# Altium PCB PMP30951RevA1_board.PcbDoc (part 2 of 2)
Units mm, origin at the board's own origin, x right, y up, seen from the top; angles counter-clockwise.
Board outline 87.63 x 58.42 mm, 2 copper layers (Top Layer, Bottom Layer), stack 1.575 mm thick; 82 components, 35 nets, 177 pads, 49 vias.
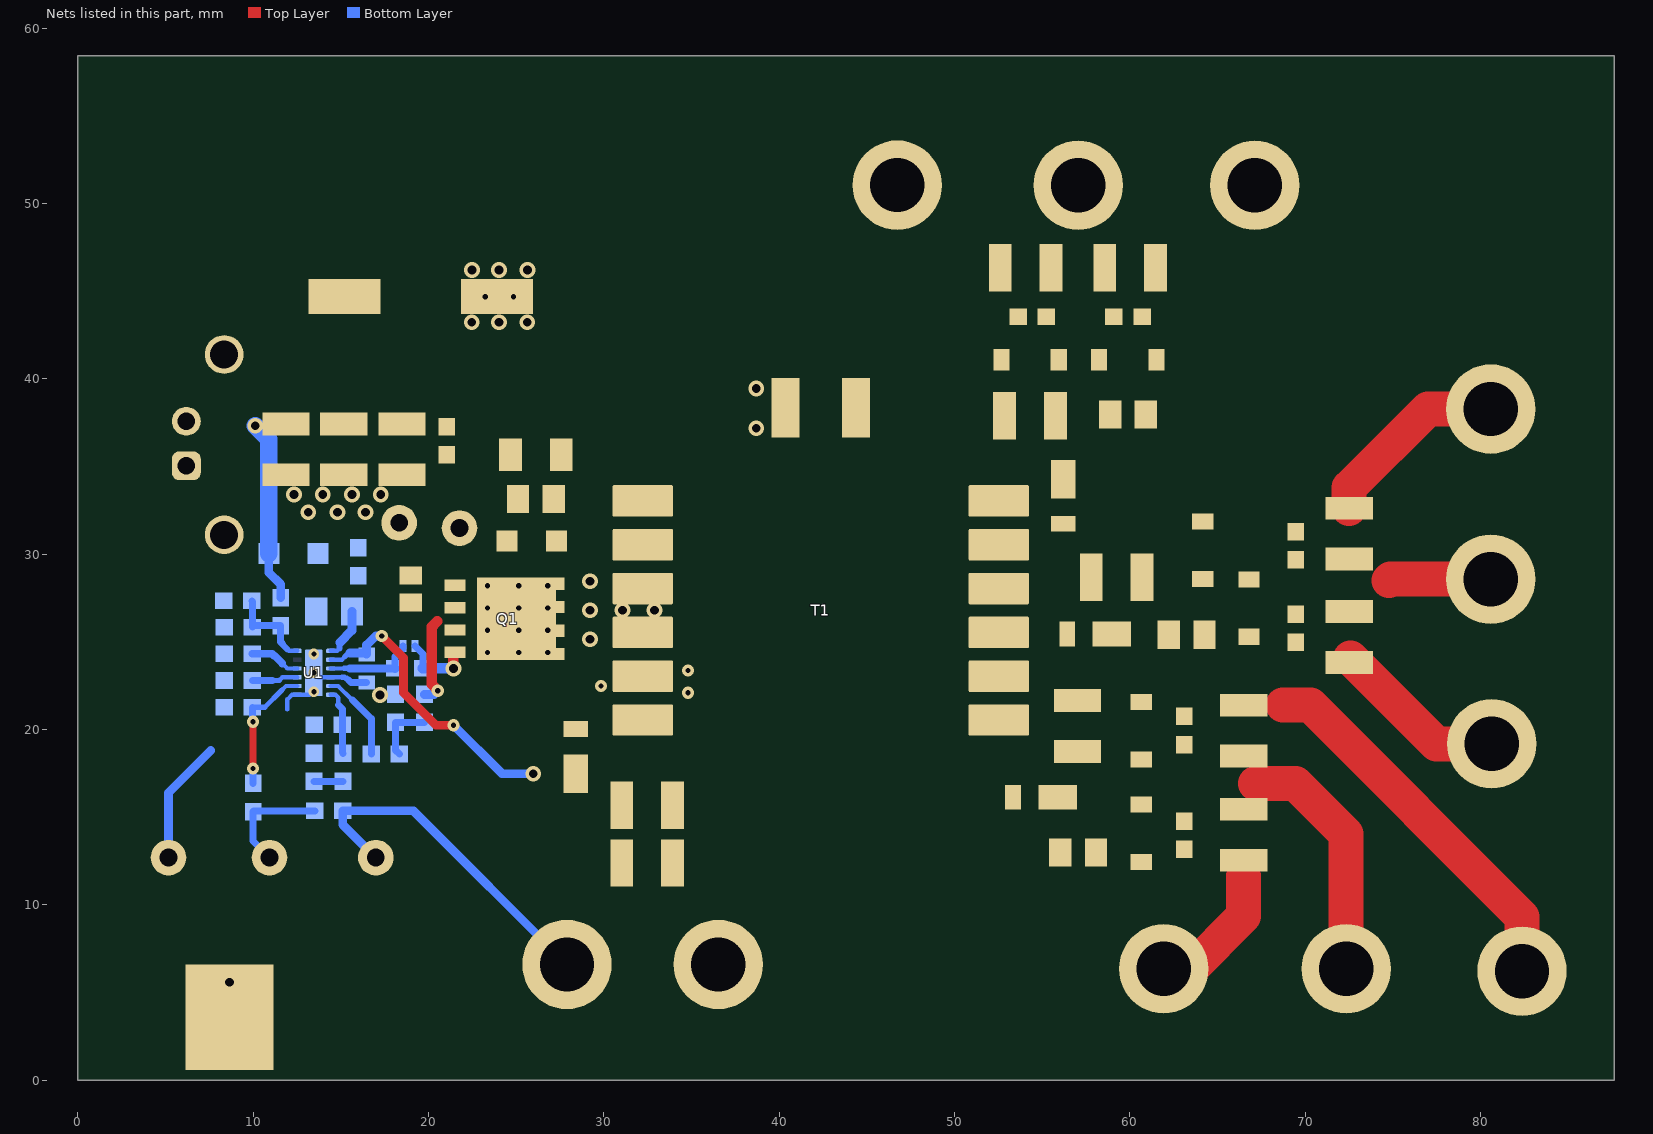
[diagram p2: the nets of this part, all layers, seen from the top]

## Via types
v1: diameter 0.9, hole 0.5, Top Layer to Bottom Layer, tented top, 19 vias
v2: diameter 0.7, hole 0.3, Top Layer to Bottom Layer, 16 vias
v3: diameter 0.9, hole 0.5, Top Layer to Bottom Layer, 4 vias
v4: diameter 0.7, hole 0.3, Top Layer to Bottom Layer, tented top, 3 vias
v5: diameter 0.7, hole 0.3, Top Layer to Bottom Layer, tented bottom, 3 vias
v6: diameter 0.6, hole 0.3, Top Layer to Bottom Layer, 3 vias
v7: diameter 0.9, hole 0.5, Top Layer to Bottom Layer, tented bottom, 1 vias

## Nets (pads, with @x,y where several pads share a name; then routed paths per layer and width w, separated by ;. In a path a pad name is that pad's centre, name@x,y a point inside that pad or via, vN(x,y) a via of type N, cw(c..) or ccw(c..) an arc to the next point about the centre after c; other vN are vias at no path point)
10Vaux: +10V_pri.1 C16.1 C24.1 C25.1 D12.1 R18.2 TP6.1 U1.2 | length 36.8
  Top Layer w0.5: v2(17.33,25.328) 18.575,24.084 18.575,22.091 20.423,20.243 v2(21.421,20.243)
  Bottom Layer w0.25: U1.2@14.412,23.978 15.062,23.978 15.211,24.126
  Bottom Layer w0.3: 15.211,24.126 15.437,24.353 15.508,24.353
  Bottom Layer w0.5: 15.508,24.353 16.398,24.353 C16.1@16.468,24.283 16.468,24.814 16.983,25.328 v2(17.33,25.328) ; TP6.1@16.992,12.688 15.109,14.571 R18.2@15.109,15.355 19.135,15.355 +10V_pri.1@27.898,6.592 ; v2(21.421,20.243) 24.196,17.468 v3(25.974,17.468)
GND: C1.2 C2.2 C3.2 C4.2 C5.2 C13.2 C16.2 C17.2 C19.2 C20.2 C21.2 C22.2 C23.2 C24.2 C25.2 GND_pri.1 Jmp1.1 pad.17 R16.1 R19.1 R20.1 R22.1 T1.5 TP2.1 TP7.1 TP8.1 U1.4 U1.7 U1.13@13.462,23.228 | length 12
  Bottom Layer w0.25: 11.948,21.136 11.948,21.712 12.214,21.978 U1.7@12.512,21.978 U1.13@13.212,21.978 ; U1.13@13.712,22.978 U1.4@14.412,22.978 15.062,22.978
  Bottom Layer w0.3: 15.062,22.978 15.209,22.978 15.265,22.922 15.331,22.922 15.437,22.816 15.437,22.81 15.468,22.778
  Bottom Layer w0.4: 15.437,22.816 15.57,22.683 C16.2@16.468,22.683
  Bottom Layer w0.5: TP8.1@5.165,12.688 5.165,16.389 7.575,18.799
  other v1: 13.132,32.385 14.808,32.385 16.408,32.385 12.319,33.401 13.97,33.401 15.628,33.401 17.272,33.401 22.47,43.234 24.018,43.234 25.637,43.234 22.479,46.205 24.027,46.205 25.646,46.205
  other v2: 23.241,44.679 24.841,44.679
  other v3: 38.693,37.176 38.693,39.442
  other v4: 34.798,22.098 29.845,22.479 34.798,23.368
  other v6: 13.462,22.153 13.462,23.228 13.462,24.303
  other v7: 17.23,21.959
Net+15V_1_1: +15V_1.1 C7.1 D2.1 R1.2 R3.2 | length 8.1
  Top Layer w2: +15V_1.1@61.934,6.338 63.488,6.338 66.502,9.352 66.502,11.642
Net+15V_2_1: +15V_2.1 C10.1 D7.1 R5.2 R7.2 | length 10.1
  Top Layer w2: C10.1@72.602,24.085 77.51,19.177 +15V_2.1@80.645,19.177
Net+15V_3_1: +15V_3.1 C14.1 D11.1 R11.2 R12.2
Net-5V_1_1: -5V_1.1 C8.2 C9.2 D3.2 R4.1 T1.8 | length 21.7
  Top Layer w2: 68.744,21.385 70.303,21.385 82.381,9.307 -5V_1.1@82.381,6.211
Net-5V_2_1: -5V_2.1 C11.2 C12.2 D8.2 R9.1 T1.10 | length 11.1
  Top Layer w2: C12.2@72.517,32.618 72.517,33.788 77.005,38.276 -5V_2.1@80.603,38.276
Net-5V_3_1: -5V_3.1 C15.2 C18.2 C19.1 D13.2 R15.1 T1.12
NetC6_2: C6.2 D4.1 R2.1
NetC7_2: C7.2 C9.1 D2.2 D3.1 R3.1 R4.2 rtn_1.1 | length 14.1
  Top Layer w2: 67.183,16.924 69.446,16.924 72.348,14.023 rtn_1.1@72.348,6.338
NetC8_1: C8.1 D1.1 R1.1
NetC10_2: C10.2 C12.1 D7.2 D8.1 R7.1 R9.2 rtn_2.1 | length 5.9
  Top Layer w2: 74.783,28.484 74.872,28.572 rtn_2.1@80.603,28.572
NetC11_1: C11.1 D5.1 R5.1
NetC13_1: C13.1 R8.1 U1.1 | length 3
  Bottom Layer w0.25: U1.1@14.412,24.478 14.784,24.478 14.931,24.625
  Bottom Layer w0.35: 14.931,24.625 14.931,24.953
  Bottom Layer w0.5: 14.931,24.953 15.628,25.65 C13.1@15.628,26.725
NetC14_2: C14.2 C18.1 D11.2 D13.1 R12.1 R15.2 rtn_3.1
NetC15_1: C15.1 D9.1 R11.1
NetC17_1: C17.1 R13.2 R14.1 | length 3.5
  Bottom Layer w0.4: R13.2@18.333,18.597 18.119,18.811 C17.1@18.119,20.397 R14.1@19.77,20.397
NetC20_1: C20.1 R6.1 R19.2 U1.12 | length 5.3
  Bottom Layer w0.25: 11.948,24.567 12.037,24.478 U1.12@12.512,24.478
  Bottom Layer w0.35: 11.664,24.886 11.664,24.851 11.948,24.567
  Bottom Layer w0.4: R19.2@9.925,27.334 9.951,27.308 C20.1@9.951,25.836 10.04,25.925 R6.1@11.564,25.925 11.564,24.986 11.664,24.886
NetC21_1: C21.1 R21.2 U1.6 | length 3.8
  Bottom Layer w0.25: U1.6@14.412,21.978 14.694,21.978 14.859,21.813 14.859,21.395
  Bottom Layer w0.4: 14.859,21.395 15.081,21.172 C21.1@15.081,20.269 15.081,18.674 R21.2@15.12,18.635
NetC22_1: C22.1 U1.9 | length 2.6
  Bottom Layer w0.25: 11.496,22.81 11.664,22.978 U1.9@12.512,22.978
  Bottom Layer w0.3: 11.089,22.788 11.474,22.788 11.496,22.81
  Bottom Layer w0.4: C22.1@9.951,22.788 11.089,22.788
NetC23_1: C23.1 R21.1 | length 1.7
  Bottom Layer w0.4: C23.1@13.469,17.035 R21.1@15.12,17.035
NetD1_2: D1.2 T1.7
NetD5_2: D5.2 T1.9
NetD6_1: D6.1 R8.2
NetD9_2: D9.2 T1.11
NetD10_1: D10.1 R10.1 U1.3 | length 5.1
  Bottom Layer w0.25: U1.3@14.412,23.478 15.179,23.478 15.184,23.483
  Bottom Layer w0.3: 15.184,23.483 15.495,23.483 15.508,23.469
  Bottom Layer w0.4: R10.1@18.081,23.483 18.081,24.153 18.531,24.603 D10.1@18.531,24.753
  Bottom Layer w0.45: 15.508,23.469 R10.1@18.067,23.469
  Bottom Layer w0.5: R10.1@18.067,23.469 R10.1@18.081,23.483
NetD10_2: D10.2 Q1.4 R10.2 | length 4.2
  Top Layer w0.6: v3(21.421,23.483) 21.421,24.31 Q1.4@21.515,24.404
  Bottom Layer w0.4: D10.2@19.231,24.753 19.681,24.303 R10.2@19.681,23.483
  Bottom Layer w0.6: R10.2@19.681,23.483 v3(21.421,23.483)
NetQ1_1: Q1.1 Q1.2 Q1.3 R14.2 R16.2 | length 5.1
  Top Layer w0.6: 20.504,26.175 20.174,25.845 20.174,22.571 v5(20.532,22.213)
  Bottom Layer w0.5: R14.2@19.77,21.997 20.316,21.997 v5(20.532,22.213)
NetR13_1: R13.1 U1.5 | length 5.1
  Bottom Layer w0.25: U1.5@14.412,22.478 14.84,22.478 15.628,21.691 15.671,21.691 15.671,21.678
  Bottom Layer w0.4: 15.671,21.678 16.72,20.629 16.733,20.629 R13.1@16.733,18.597
NetR17_1: R17.1 R22.2 U1.8 | length 7.4
  Top Layer w0.4: v5(9.991,17.768) v5(9.991,20.435)
  Bottom Layer w0.25: 11.603,22.213 11.868,22.478 U1.8@12.512,22.478
  Bottom Layer w0.3: R22.2@9.951,21.264 10.654,21.264 11.603,22.213
  Bottom Layer w0.4: R22.2@9.951,21.264 9.951,20.475 v5(9.991,20.435) ; R17.1@9.991,16.917 v5(9.991,17.768)
NetR17_2: R17.2 R18.1 TP5.1 | length 6.6
  Bottom Layer w0.4: TP5.1@10.929,12.688 9.991,13.626 R17.2@9.991,15.317 10.029,15.355 R18.1@13.509,15.355
NetR20_2: R20.2 U1.10 | length 2.9
  Bottom Layer w0.25: 11.664,23.762 11.948,23.478 U1.10@12.512,23.478
  Bottom Layer w0.435: R20.2@9.951,24.312 11.08,24.312 11.183,24.209 11.217,24.209 11.664,23.762
SW-aux: D12.2 T1.6
SW_primary: D4.2 Q1.5 Q1.6 Q1.7 Q1.8 Q1.9 T1.3 T1.4 TP3.1
  other v1: 29.21,25.146 29.21,26.797 31.07,26.797 32.893,26.797 29.21,28.448
  other v2: 23.368,24.384 25.146,24.384 26.797,24.384 23.368,25.654 25.146,25.654 26.797,25.654 23.368,26.924 25.146,26.924 26.797,26.924 23.368,28.194 25.146,28.194 26.797,28.194
VIN: C1.1 C2.1 C3.1 C4.1 C5.1 C6.1 D6.2 Jmp1.2 R2.2 R6.2 T1.1 T1.2 TP1.1 | length 10.4
  Bottom Layer w0.5: D6.2@10.889,30.036 10.889,28.95 11.564,28.275 R6.2@11.564,27.525
  Bottom Layer w1: v1(10.118,37.326) 10.889,36.555 D6.2@10.889,30.036
pads on no net: U1.11 U1.13@13.462,22.543 U1.13@13.462,23.913

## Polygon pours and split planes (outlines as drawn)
Net+15V_1_1 on Top Layer "TOP_LAYER_NET+15V_1_1_P034" (solid, remove dead copper, pour order 34): 57.398,11.96 58.817,10.541 67.867,10.541 68.744,11.418 68.744,13.095 68.138,13.701 59.819,13.701 59.189,14.33 57.736,14.33 57.398,13.992
Net-5V_1_1 on Top Layer "TOP_LAYER_NET-5V_1_1_P033" (solid, remove dead copper, pour order 33): 50.8,22.098 54.455,22.098 56.36,20.193 68.662,20.193 69.446,20.977 69.446,21.841 68.744,22.543 64.582,22.543 63.552,23.573 57.697,23.573 57.307,23.963 50.804,23.963
NetC7_2 on Top Layer "TOP_LAYER_NETC7_2_P032" (solid, remove dead copper, pour order 32): 59.991,15.256 61.023,14.224 68.157,14.224 68.453,14.52 68.453,19.329 68.102,19.68 60.874,19.68 59.991,18.796
NetC8_1 on Top Layer "TOP_LAYER_NETC8_1_P030" (solid, remove dead copper, pour order 30): 54.805,11.991 55.071,11.725 56.532,11.725 57.057,12.251 57.057,14.426 58.373,15.742 58.373,19.572 58.157,19.788 55.227,19.788 54.805,19.365
NetD1_2 on Top Layer "TOP_LAYER_NETD1_2_P029" (solid, remove dead copper, pour order 29): 50.488,16.51 ccw(c52.282,16.51) 52.282,14.717 53.285,14.717 ccw(c53.285,15.742) 54.31,15.742 54.31,21.299 ccw(c53.966,21.299) 53.966,21.643 51.154,21.643 ccw(c51.154,20.977) 50.488,20.977
Net+15V_2_1 on Top Layer "TOP_LAYER_NET+15V_2_1_P028" (solid, remove dead copper, pour order 28): 63.552,26.416 63.552,24.162 64.854,22.86 74.364,22.86 75.235,23.731 75.235,25.034 74.741,25.527 67.722,25.527 66.514,26.735 63.871,26.735
NetC10_2 on Top Layer "TOP_LAYER_NETC10_2_P027" (solid, remove dead copper, pour order 27): 63.552,27.403 66.499,27.403 67.867,26.035 74.285,26.035 75.235,26.985 75.235,29.457 74.339,30.353 64.554,30.353 63.552,29.351
NetC11_1 on Top Layer "TOP_LAYER_NETC11_1_P026" (solid, remove dead copper, pour order 26): 57.802,26.447 58.851,26.447 59.743,27.34 59.743,29.627 60.156,30.04 61.4,30.04 62.865,28.575 62.865,24.404 62.596,24.135 58.108,24.135 57.802,24.441
Net-5V_2_1 on Top Layer "TOP_LAYER_NET-5V_2_1_P025" (solid, remove dead copper, pour order 25): 50.804,28.941 55.553,28.941 60.267,33.655 74.803,33.655 75.235,33.223 75.235,30.986 74.982,30.734 60.19,30.734 59.496,30.04 59.496,27.801 58.883,27.189 50.777,27.189
NetD5_2 on Top Layer "TOP_LAYER_NETD5_2_P023" (solid, remove dead copper, pour order 23): 56.769,26.447 cw(c56.769,25.994) 57.222,25.994 57.222,24.941 cw(c56.902,24.941) 56.902,24.62 50.883,24.62 cw(c50.883,25.014) 50.488,25.014 50.488,25.908 cw(c51.028,25.908) 51.028,26.447
Net+15V_3_1 on Top Layer "TOP_LAYER_NET+15V_3_1_P022" (solid, remove dead copper, pour order 22): 60.156,49.459 63.009,52.312 67.966,52.312 67.966,50.818 66.502,49.354 66.502,41.092 62.101,36.691 60.156,36.691
NetC14_2 on Top Layer "TOP_LAYER_NETC14_2_P021" (solid, remove dead copper, pour order 21): 59.394,40.437 59.584,40.628 59.584,51.986 58.243,53.328 55.899,53.328 54.695,52.124 54.695,40.437
NetC15_1 on Top Layer "TOP_LAYER_NETC15_1_P020" (solid, remove dead copper, pour order 20): 55.01,33.035 58.243,33.035 59.496,34.288 59.496,38.973 59.027,39.442 55.01,39.442
NetD9_2 on Top Layer "TOP_LAYER_NETD9_2_P019" (solid, remove dead copper, pour order 19): 51.028,29.576 54.309,29.576 ccw(c54.309,32.116) 56.105,30.32 56.549,30.764 ccw(c55.323,31.99) 57.057,31.99 57.057,32.176 ccw(c56.807,32.176) 56.807,32.426 56.041,32.426 ccw(c56.041,31.053) 55.071,32.024 54.898,31.851 cw(c53.992,32.758) 53.992,31.476 50.877,31.476 ccw(c50.877,30.976) 50.377,30.976 50.377,29.938 ccw(c50.758,29.938) 50.758,29.557
Net-5V_3_1 on Top Layer "TOP_LAYER_NET-5V_3_1_P018" (solid, remove dead copper, pour order 18): 54.314,32.176 47.743,32.176 43.519,36.4 43.519,50.026 45.424,51.931 50.758,51.931 54.06,48.629 54.06,36.801 54.56,36.301 54.56,32.404 54.385,32.229
GND on Top Layer "TOP_LAYER_GND_P017" (solid, remove dead copper, pour order 17): 41.106,36.075 38.101,36.075 37.677,36.499 37.677,40.247 38.058,40.628 41.106,40.628
GND on Top Layer "TOP_LAYER_GND_P016" (solid, remove dead copper, pour order 16): 20.696,47.486 20.696,44.359 22.268,42.787 25.828,42.787 27.225,44.184 27.225,47.486
GND on Top Layer "TOP_LAYER_GND_P012" (solid, remove dead copper, pour order 12): 31.993,17.133 31.993,6.318 34.259,4.052 37.925,4.052 41.106,7.233 41.106,17.051
10Vaux on Top Layer "TOP_LAYER_10VAUX_P000" (solid, remove dead copper, pour order 0): 30.244,18.597 31.708,17.133 31.708,6.273 29.487,4.052 26.519,4.052 24.487,6.084 24.487,16.915 26.169,18.597
SW-aux on Top Layer "TOP_LAYER_SW-AUX_P001" (solid, remove dead copper, pour order 1): 34.121,21.324 34.121,20.01 cw(c33.359,20.01) 33.359,19.248 28.032,19.248 cw(c28.032,19.888) 27.392,19.888 27.392,20.437 cw(c28.533,20.437) 28.533,21.578 33.867,21.578 cw(c33.867,21.324)
GND on Top Layer "TOP_LAYER_GND_P006" (solid, remove dead copper, pour order 6): 24.235,9.121 24.235,6.141 22.146,4.052 5.546,4.052 4.403,5.195 4.403,15.359 4.403,36.175 22.235,36.175 23,35.41 23,33.474 22.743,33.218 20.832,33.218 20.083,32.469 20.083,30.612 20.659,30.036 20.659,29.104 19.83,28.275 18.22,28.275 17.754,27.809 17.754,26.404 17.983,26.175 19.363,26.175 22.463,23.075 28.97,23.075 29.759,23.864 39.021,23.864 41.106,21.779 41.106,10.656 39.571,9.121
NetQ1_1 on Top Layer "TOP_LAYER_NETQ1_1_P005" (solid, remove dead copper, pour order 5): 22.146,25.328 19.365,25.328 18.133,26.561 18.133,27.721 18.221,27.809 19.75,27.809 20.56,28.619 22.146,28.619
NetC6_2 on Top Layer "TOP_LAYER_NETC6_2_P004" (solid, remove dead copper, pour order 4): 26.445,30.036 28.064,30.036 28.528,30.5 28.528,36.371 28.198,36.701 26.746,36.701 26.445,36.4
SW_primary on Top Layer "TOP_LAYER_SW_PRIMARY_P003" (solid, remove dead copper, pour order 3): 40.407,29.007 cw(c40.407,28.309) 41.106,28.309 41.106,25.067 cw(c40.376,25.067) 40.376,24.337 33.126,24.341 29.214,24.341 ccw(c29.214,23.377) 28.532,24.059 28.531,24.058 cw(c27.568,25.021) 27.568,23.659 23.14,23.659 cw(c23.14,24.126) 22.672,24.126 22.672,28.525 ccw(c21.434,28.309) 22.323,29.197 20.974,30.546 cw(c22.206,31.778) 20.464,31.778 cw(c21.504,31.778) 21.504,32.817 22.285,32.817 cw(c22.285,32.238) 22.865,32.238 ccw(c23.325,32.238) 23.325,31.778 24.811,31.778 cw(c24.811,31.118) 25.47,31.118 25.47,29.782 ccw(c26.245,29.782) 26.245,29.007
VIN on Top Layer "TOP_LAYER_VIN_P002" (solid, remove dead copper, pour order 2): 4.403,36.818 22.323,36.818 23.54,35.601 23.54,32.819 24.24,32.119 25.829,32.119 26.12,32.41 26.12,36.376 26.77,37.026 28.848,37.026 29.398,36.476 29.398,30.005 30.12,29.284 33.938,29.284 34.375,29.72 34.375,39.866 31.747,42.494 19.726,42.494 18.037,44.184 18.037,46.201 17.133,47.105 6.181,47.105 4.403,45.327
SW_primary on Bottom Layer "BOTTOM_LAYER_SW_PRIMARY_P035" (solid, remove dead copper, pour order 35): 33.856,29.009 cw(c33.856,28.321) 34.544,28.321 34.544,26.009 cw(c32.004,26.009) 32.004,23.469 23.115,23.469 cw(c23.115,24.183) 22.401,24.183 22.401,28.068 ccw(c19.861,28.068) 21.657,29.864 20.974,30.546 cw(c22.206,31.778) 20.464,31.778 cw(c21.504,31.778) 21.504,32.817 21.895,32.817 cw(c21.895,30.913) 23.241,32.26 23.325,32.176 ccw(c24.468,33.319) 24.468,31.703 25.123,31.703 cw(c25.123,30.901) 25.924,30.901 25.924,29.611 ccw(c26.527,29.611) 26.527,29.009
GND on Bottom Layer "BOTTOM_LAYER_GND_P015" (solid, remove dead copper, pour order 15): 4.403,29.499 19.627,29.499 20.083,29.954 20.083,32.469 20.832,33.218 23.141,33.218 24.24,32.119 25.829,32.119 26.12,32.41 26.12,36.376 26.77,37.026 28.848,37.026 29.398,36.476 29.398,30.005 30.116,29.287 34.89,29.287 35.137,29.041 35.137,24.738 33.474,23.075 28.97,23.075 22.879,23.075 17.193,17.389 17.193,15.699 15.314,13.82 8.583,13.82 4.403,9.64 4.403,5.195 5.546,4.052 37.925,4.052 41.106,7.233 41.106,46.513 37.677,49.942 5.589,49.942 4.403,48.756
NetD6_1 on Bottom Layer "BOTTOM_LAYER_NETD6_1_P013" (solid, remove dead copper, pour order 13): 14.44,29.417 14.895,29.872 16.544,29.872 16.708,30.036 16.708,31.094 16.492,31.311 13.158,31.311 12.912,31.065 12.912,29.499 12.994,29.417
NetC13_1 on Bottom Layer "BOTTOM_LAYER_NETC13_1_P011" (solid, remove dead copper, pour order 11): 14.931,25.709 16.535,25.709 17.23,26.404 17.23,28.817 16.722,29.325 14.994,29.325 14.796,29.127 14.796,25.844
GND on Bottom Layer "BOTTOM_LAYER_GND_P010" (solid, remove dead copper, pour order 10): 10.322,20.435 9.349,20.435 9.151,20.632 9.151,27.734 8.721,28.165 7.088,28.165 6.689,27.765 6.689,18.343 7.197,17.835 11.036,17.835 12.277,19.076 12.277,21.814 12.079,22.011
GND on Bottom Layer "BOTTOM_LAYER_GND_P009" (solid, remove dead copper, pour order 9): 13.962,22.478 13.962,21.063 14.281,20.744 14.281,17.922 14.194,17.835 12.714,17.835 12.628,17.921 12.628,21.343 12.963,21.678 12.963,22.478
GND on Bottom Layer "BOTTOM_LAYER_GND_P008" (solid, remove dead copper, pour order 8): 13.874,30.361 11.214,30.361 10.889,30.036 10.889,28.506 12.289,27.106 12.289,25.401 12.963,24.728 12.963,23.712 13.962,23.711 13.962,24.922 14.423,25.4 14.423,29.813
GND on Bottom Layer "BOTTOM_LAYER_GND_P007" (solid, remove dead copper, pour order 7): 15.743,22.153 16.699,21.197 18.594,21.197 18.844,21.447 18.844,22.478 18.575,22.747 17.38,22.747 17.152,22.975 15.833,22.975 15.743,22.885

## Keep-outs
Keep-Out Layer:
  text ".Layer_Name" at 14.656,-21.806 h1.52

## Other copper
Top Layer:
  text ".Layer_Name" at 14.656,-21.806 h1.52
Bottom Layer:
  text ".Layer_Name" at 14.656,-21.806 h1.52

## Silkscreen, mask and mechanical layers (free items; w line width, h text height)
Top Overlay:
  text "12/2020" at 81.475,56.877 h0.8
  text "'.PRJ_Number'.PCB_Rev" at 6.604,53.213 h2
  text "PSR Flyback" at 10.329,51.356 h1
  text "VIN" at 3.832,37.076 h1 r90
  text "GND" at 3.832,32.437 h1 r90
  text "AGND" at 3.332,9.827 h1
  text "NWA" at 9.3,9.827 h1
  text "priFB" at 15.124,9.624 h1
  text ".Layer_Name" at 14.656,-21.806 h1.52
Bottom Overlay:
  text ".Layer_Name" at 14.656,-21.806 h1.52
Top Paste:
  text ".Layer_Name" at 14.656,-21.806 h1.52
Bottom Paste:
  text ".Layer_Name" at 14.656,-21.806 h1.52
Top Solder:
  text ".Layer_Name" at 14.656,-21.806 h1.52
  text ".Layer_Name" at 14.656,-21.806 h1.52
Bottom Solder:
  text "'.PRJ_Number'.PCB_Rev" at 37.211,13.82 h2 r270
  text ".Layer_Name" at 14.656,-21.806 h1.52
Drill Guide:
  text ".Layer_Name" at 14.656,-21.806 h1.52
M1 Board Outline:
  the board outline again, w0.254
  text ".Layer_Name" at 14.656,-21.806 h1.52
M2 Board Dimensions:
  rectangle: 0,-6.985 3.175,-3.81
  rectangle: 3.175,-10.16 12.7,-6.985
  lines w0.178: 0,-6.985 25.4,-6.985 ; 3.175,-10.16 3.175,-3.81 ; 6.35,-10.16 6.35,-3.81 ; 12.7,-10.16 12.7,-3.81 ; 19.05,-10.16 19.05,-3.81 ; 0,-10.16 25.4,-10.16 25.4,-3.81 0,-3.81 0,-10.16
  text ".Layer_Name" at 14.656,-21.806 h1.52
M3 3D STEP Top:
  text ".Layer_Name" at 14.656,-21.806 h1.52
M4 3D STEP Bottom:
  text ".Layer_Name" at 14.656,-21.806 h1.52
M5 Assembly Top:
  lines w0.254: -7.417,-23.626 160.223,-23.626 ; -7.417,-18.462 160.274,-18.462 ; -7.417,-13.297 -7.417,-28.791 94.31,-28.791 160.274,-28.791 160.274,-13.297 -7.404,-13.297 -7.404,-28.791 32.614,-28.791 ; 55.194,-28.791 55.194,-13.297 ; 87.376,-18.462 87.376,-13.297 ; 108.712,-18.462 108.712,-13.297 ; 124.511,-28.956 124.511,-23.804
  text "COMPONENTS MARKED 'DNP' SHOULD NOT BE POPULATED." at 29.299,-8.09 h1.52
  text "ASSEMBLY VARIANT:" at 29.286,-11.024 h1.52
  text ".VariantName" at 55.601,-11.024 h1.52
  text "PCB VIEWED FROM TOP SIDE" at -5.804,-16.654 h1.52
  text "BOARD #:" at 57.099,-16.654 h1.52
  text ".PRJ_Number" at 70.955,-16.654 h1.52
  text "REV:" at 92.405,-16.654 h1.52
  text ".PCB_Rev" at 99.809,-16.654 h1.52
  text "SVN REV:" at 113.69,-16.654 h1.52
  text ".VersionControl_RevNumber" at 126.543,-16.654 h1.52
  text "TID #:" at 57.099,-21.819 h1.52
  text ".TID" at 70.955,-21.819 h1.52
  text "PLOT NAME =" at -5.804,-27.034 h1.52
  text ".plot_File_Name" at 14.656,-27.034 h1.52
  text "GENERATED    :" at 57.15,-27.034 h1.52
  text ".Print_Date" at 79.235,-27.034 h1.52
  text ".Print_Time" at 97.752,-27.034 h1.52
  text "TEXAS INSTRUMENTS" at 129.87,-27.034 h1.52
M6 Assembly Bottom:
  lines w0.254: -7.429,-18.474 160.261,-18.474 ; -7.379,-23.639 160.261,-23.639 ; 28.334,-28.969 28.334,-23.817 ; 44.133,-18.474 44.133,-13.31 ; 65.468,-18.474 65.468,-13.31 ; 97.65,-28.804 97.65,-13.31 ; 120.231,-28.804 160.249,-28.804 160.249,-13.31 -7.429,-13.31 -7.429,-28.804 58.534,-28.804 160.261,-28.804 160.261,-13.31
  text "COMPONENTS MARKED 'DNP' SHOULD NOT BE POPULATED." at 154.991,-8.077 h1.52
  text ".VariantName" at 128.473,-11.024 h1.52
  text "ASSEMBLY VARIANT:" at 154.864,-11.024 h1.52
  text ".VersionControl_RevNumber" at 26.302,-16.667 h1.52
  text "SVN REV:" at 39.154,-16.667 h1.52
  text ".PCB_Rev" at 53.035,-16.667 h1.52
  text "REV:" at 60.439,-16.667 h1.52
  text ".PRJ_Number" at 81.89,-16.667 h1.52
  text "BOARD #:" at 95.745,-16.667 h1.52
  text "PCB VIEWED FROM BOTTOM SIDE" at 158.648,-16.667 h1.52
  text ".TID" at 81.89,-21.831 h1.52
  text "TID #:" at 95.745,-21.831 h1.52
  text "TEXAS INSTRUMENTS" at 22.974,-27.047 h1.52
  text ".Print_Time" at 55.093,-27.047 h1.52
  text ".Print_Date" at 73.609,-27.047 h1.52
  text "GENERATED    :" at 95.694,-27.047 h1.52
  text ".plot_File_Name" at 138.189,-27.047 h1.52
  text "PLOT NAME =" at 158.648,-27.047 h1.52
M9 Title Sheet:
  drawing of 57 lines, arcs and shapes, not listed
  text "1" at 18.792,204.127 h1.78
  text "2" at 82.182,204.127 h1.78
  text "3" at 145.411,204.127 h1.78
  text "4" at 209.08,204.127 h1.78
  text "5" at 272.555,204.127 h1.78
  text "6" at 336.182,204.127 h1.78
  text "A" at -10.579,175.095 h1.78
  text "A" at 365.341,175.095 h1.78
  text "B" at -10.579,114.643 h1.78
  text "B" at 365.341,114.643 h1.78
  text "C" at -10.579,54.318 h1.78
  text "C" at 365.341,54.318 h1.78
  text "PROJECT TITLE:" at 288.125,7.048 h1.14
  text ".PRJ_Title" at 289.395,3.662 h1.78
  text "DESIGNED FOR:" at 288.125,-0.597 h1.14
  text ".PRJ_Customer" at 289.395,-4.153 h1.78
  text "D" at -10.579,-5.88 h1.78
  text "D" at 365.341,-5.88 h1.78
  text "FILE NAME:" at 288.125,-8.217 h1.14
  text ".PCB_File_Name_No_Path" at 289.395,-11.265 h1.78
  text "Texas Instruments (TI) and/or its licensors do not warrant the accuracy or completeness of this specification" at 161.9,-15.376 h1.14
  text "ENGINEER:" at 288.125,-15.583 h1.14
  text "LAYOUT BY:" at 326.352,-15.583 h1.14
  text "or any information contained therein. TI and/or its licensors do not warrant that this design will meet" at 160.757,-18.237 h1.14
  text ".PRJ_Engineer" at 289.395,-19.52 h1.78
  text ".PCB_Layout" at 327.635,-19.52 h1.78
  text "the specifications, will be suitable for your application or fit for any particular purpose, or will operate in" at 160.757,-21.099 h1.14
  text ".Layer_Name" at 14.656,-21.806 h1.52
  text "ALTIUM DESIGNER VERSION:" at 326.352,-23.457 h1.14
  text "an implementation. TI and/or its licensors do not warrant that the design is production worthy. You should" at 160.757,-23.961 h1.14
  text "completely validate and test your design implementation to confirm the system functionality for your application." at 161.9,-26.822 h1.14
  text ".print_Scale" at 289.395,-26.843 h1.78
  text ".Application_BuildNumber" at 327.635,-26.843 h1.78
  text "1" at 18.792,-32.093 h1.78
  text "2" at 82.182,-32.093 h1.78
  text "3" at 145.411,-32.093 h1.78
  text "4" at 209.08,-32.093 h1.78
  text "5" at 272.555,-32.093 h1.78
  text "6" at 336.182,-32.093 h1.78
M10 Fab Notes:
  drawing of 189 lines, arcs and shapes, not listed
  text "DESIGN INFORMATION" at 314.503,161.447 h1.52
  text "MIN. TRACK WIDTH:" at 298.131,158.091 h1.52
  text "8" at 325.976,158.091 h1.52
  text "MIL" at 329.907,158.091 h1.52
  text "MIN. CLEARANCE:" at 298.131,154.938 h1.52
  text "0.2" at 324.452,154.938 h1.52
  text "mm" at 329.907,154.938 h1.52
  text "MIN. VIA PAD SIZE:" at 298.131,151.785 h1.52
  text "24" at 325.214,151.785 h1.52
  text "MIL" at 329.907,151.785 h1.52
  text "0.05mm (2MIL)" at 315.784,148.486 h1.52
  text "MINIMUM ANNULAR RING" at 289.769,148.277 h1.52
  text "EXTERNAL" at 333.768,148.277 h1.52
  text "PER" at 294.849,145.48 h1.52
  text "IPC-D-275 CLASS 2 LEVEL C" at 300.437,145.48 h1.52
  text "MIL, HOLES" at 338.238,142.928 h1.52
  text "+/-" at 328.27,142.709 h1.52
  text "+/-" at 349.961,142.709 h1.52
  text "REGISTRATION TOLERANCES:" at 289.769,142.682 h1.52
  text "METAL" at 320.243,142.682 h1.52
  text "5" at 334.879,142.683 h1.52
  text "3" at 356.037,142.683 h1.52
  text "MIL" at 358.99,142.682 h1.52
  text "HOLE SIZE TOLERANCE (UNLESS OTHERWISE SPECIFIED):" at 289.769,140.185 h1.52
  text "+/-" at 349.961,140.112 h1.52
  text "3" at 356.037,140.085 h1.52
  text "MIL" at 358.99,140.085 h1.52
  text "MATERIAL:" at 287.87,136.589 h1.52
  text "FR-4 High Tg" at 312.926,133.324 h1.52
  text "X" at 309.257,133.122 h1.52
  text "FR-408" at 298.563,133.007 h1.52
  text "OTHER" at 336.358,133.007 h1.52
  text "62 MIL (1.6mm) +/-10%" at 306.694,129.374 h1.52
  text "X" at 303.643,129.312 h1.52
  text "THICKNESS:" at 289.769,129.165 h1.52
  text "OTHER" at 339.33,129.165 h1.52
  text "TOLERANCE:" at 289.769,125.652 h1.52
  text "X" at 311.314,125.652 h1.52
  text "ANSI IPC-6012 TYPE 3 CLASS 2" at 315.836,125.652 h1.52
  text "OTHER +/-" at 315.835,121.989 h1.52
  text "BOW & TWIST:" at 289.769,118.302 h1.52
  text "X" at 311.314,118.302 h1.52
  text "ANSI IPC-6012 TYPE 3 CLASS 2" at 315.836,118.302 h1.52
  text "OTHER +/-" at 315.835,114.576 h1.52
  text "DRILLING:" at 287.87,111.258 h1.52
  text "NC_DRILL FILES" at 332.599,108.586 h1.52
  text "REFERENCE:" at 289.769,108.486 h1.52
  text "X" at 306.463,108.484 h1.52
  text "AS SHOWN" at 310.984,108.486 h1.52
  text "X" at 329.348,108.486 h1.52
  text "OTHER" at 340.168,104.873 h1.52
  text "PTH COPPER THICKNESS:" at 289.761,104.783 h1.52
  text "X" at 318.697,104.783 h1.52
  text "20-30 um" at 321.948,104.783 h1.52
  text "BOARD FINISH:" at 287.87,101.034 h1.52
  text "SILKSCREEN:" at 291.812,98.237 h1.52
  text "X" at 316.14,98.237 h1.52
  text "TOP" at 319.112,98.237 h1.52
  text "X" at 329.094,98.237 h1.52
  text "BOTTOM" at 332.091,98.237 h1.52
  text "SILKSCREEN COLOR:" at 291.812,94.295 h1.52
  text "X" at 316.115,94.295 h1.52
  text "WHITE" at 319.112,94.295 h1.52
  text "OTHER" at 332.091,94.295 h1.52
  text "X" at 319.442,90.652 h1.52
  text "GREEN" at 322.439,90.652 h1.52
  text "OTHER" at 338.136,90.652 h1.52
  text "SOLDER RESIST COLOR:" at 291.812,90.477 h1.52
  text "X" at 319.442,86.734 h1.52
  text "MATTE" at 322.439,86.734 h1.52
  text "SEMI-GLOSS" at 338.125,86.717 h1.52
  text "IMMERSION GOLD (ENIG)" at 314.819,82.345 h1.52
  text "ENEPIG" at 348.793,82.162 h1.52
  text "SURFACE FINISH:" at 287.87,82.136 h1.52
  text "X" at 310.298,82.136 h1.52
  text "IMM. TIN/SILVER OR EQUIV" at 296.24,78.649 h1.52
  text "OTHER" at 332.599,78.549 h1.52
  text "ARRAY/PANEL:" at 287.87,74.602 h1.52
  text "CUT AND TRIM PER M1 BOARD OUTLINE" at 314.819,74.393 h1.52
  text "N.C. ROUTE" at 314.819,70.94 h1.52
  text "X" at 332.295,70.94 h1.52
  text "V. SCORE" at 336.816,70.94 h1.52
  text "CERTIFICATION:" at 287.87,67.66 h1.52
  text "MATERIALS AND WORKMANSHIP FOR ALL PCBS" at 306.285,67.66 h1.52
  text "TO MEET OR EXCEED THE REQUIREMENTS OF:" at 306.285,65.271 h1.52
  text "X" at 297.078,62.003 h1.52
  text "ANSI IPC-A-600F CLASS ->" at 300.329,62.003 h1.52
  text "X" at 342.188,62.003 h1.52
  text "2" at 344.982,62.003 h1.52
  text "1" at 336.981,61.965 h1.52
  text "3" at 353.973,61.965 h1.52
  text "X" at 317.702,58.252 h1.52
  text "RoHS" at 320.953,58.252 h1.52
  text "OTHER" at 337.321,58.252 h1.52
  text "PER ORDER" at 347.407,58.252 h1.52
  text "ALL BOARDS MUST MEET OR EXCEED UL94-V0 REQUIREMENTS." at 288.569,54.345 h1.52
  text "PCB MUST BEAR THE UL94V-0 UL REGISTERED MATERIAL ID NUMBER" at 288.569,51.397 h1.52
  text "ADDITIONAL REQUIREMENTS:" at 287.87,47.094 h1.52
  text "MICROSECTION:" at 289.769,44.373 h1.52
  text "YES" at 312.775,44.373 h1.52
  text "REQUIRED" at 334.657,40.707 h1.52
  text "BARE BOARD ELEC. TEST:" at 289.769,40.634 h1.52
  text "NONE" at 322.935,40.634 h1.52
  text "X" at 331.66,40.634 h1.52
  text "PER ORDER" at 349.693,40.634 h1.52
  text "XX MIL VIAS REQUIRE NON-CONDUCTIVE FILL AND PLANARIZE" at 294.04,35.428 h1.5
  text "XX MIL VIAS REQUIRE CONDUCTIVE FILL AND PLANARIZE" at 294.243,32.787 h1.52
  text "OUTER XX MIL TRACES REQUIRE 50 OHM SINGLE-ENDED IMPEDANCE" at 294.218,28.637 h1.47
  text "LAYER 2 & 3 (INNER LAYERS) XX MIL WIDE, XX MIL SPACE / TRACES REQUIRE 100 OHM DIFFERENTIAL IMPEDANCE" at 294.015,22.65 h1.52
  text ".Layer_Name" at 14.656,-21.806 h1.52
M11 Gerber Information:
  lines w0.254: -7.417,-23.626 160.223,-23.626 ; -7.417,-18.462 160.274,-18.462 ; -7.417,-13.297 -7.417,-28.791 94.31,-28.791 160.274,-28.791 160.274,-13.297 -7.404,-13.297 -7.404,-28.791 32.614,-28.791 ; 55.194,-28.791 55.194,-13.297 ; 87.376,-18.462 87.376,-13.297 ; 108.712,-18.462 108.712,-13.297 ; 124.511,-28.956 124.511,-23.804
  text "ALL ARTWORK VIEWED FROM TOP SIDE" at -5.804,-16.654 h1.52
  text "BOARD #:" at 57.099,-16.654 h1.52
  text ".PRJ_Number" at 70.955,-16.654 h1.52
  text "REV:" at 92.405,-16.654 h1.52
  text ".PCB_Rev" at 99.809,-16.654 h1.52
  text "SVN REV:" at 113.69,-16.654 h1.52
  text ".VersionControl_RevNumber" at 126.543,-16.654 h1.52
  text "LAYER NAME =" at -5.804,-21.806 h1.52
  text "TID #:" at 57.099,-21.819 h1.52
  text ".TID" at 70.955,-21.819 h1.52
  text "PLOT NAME =" at -5.804,-27.034 h1.52
  text ".plot_File_Name" at 14.656,-27.034 h1.52
  text "GENERATED    :" at 57.15,-27.034 h1.52
  text ".Print_Date" at 79.235,-27.034 h1.52
  text ".Print_Time" at 97.752,-27.034 h1.52
  text "TEXAS INSTRUMENTS" at 129.87,-27.034 h1.52
M12 Stackup:
  drawing of 191 lines, arcs and shapes, not listed
  text "Layer" at 249.119,194.31 h1.52
  text "Name" at 259.531,194.31 h1.52
  text "Material" at 283.147,194.31 h1.52
  text "Thickness" at 304.985,194.31 h1.52
  text "Constant" at 321.49,194.31 h1.52
  text "Board Layer Stack" at 335.965,194.31 h1.52
  text "Top Overlay" at 259.531,191.262 h1.52
  text "Top Solder" at 259.531,188.214 h1.52
  text "Solder Resist" at 283.147,188.214 h1.52
  text "0.40mil" at 304.985,188.214 h1.52
  text "3.5" at 321.49,188.214 h1.52
  text "1" at 249.119,185.166 h1.52
  text "Top Layer" at 259.531,185.166 h1.52
  text "Copper" at 283.147,185.166 h1.52
  text "1.40mil" at 304.985,185.166 h1.52
  text "Dielectric1" at 259.531,182.118 h1.52
  text "FR-4" at 283.147,182.118 h1.52
  text "59.20mil" at 304.985,182.118 h1.52
  text "4.8" at 321.49,182.118 h1.52
  text "2" at 249.119,179.07 h1.52
  text "Bottom Layer" at 259.531,179.07 h1.52
  text "Copper" at 283.147,179.07 h1.52
  text "1.40mil" at 304.985,179.07 h1.52
  text "Bottom Solder" at 259.531,176.022 h1.52
  text "Solder Resist" at 283.147,176.022 h1.52
  text "0.40mil" at 304.985,176.022 h1.52
  text "3.5" at 321.49,176.022 h1.52
  text "Bottom Overlay" at 259.531,172.974 h1.52
  text ".Layer_Name" at 14.656,-21.806 h1.52
M13 Component Bodies Top:
  text ".Layer_Name" at 14.656,-21.806 h1.52
M14 Component Bodies Bottom:
  text ".Layer_Name" at 14.656,-21.806 h1.52
M15 Courtyards Top:
  text ".Layer_Name" at 14.656,-21.806 h1.52
M16 Courtyards Bottom:
  text ".Layer_Name" at 14.656,-21.806 h1.52
Drill Drawing:
  circle w0.254: c136.241,71.527 r0.703
  lines w0.254: 135.538,75.392 136.944,75.392 136.241,73.986 135.538,75.392 ; 135.538,77.149 136.944,77.149 136.944,78.554 135.538,78.554 135.538,77.149 ; 135.538,80.662 135.89,80.662 136.241,80.311 136.593,80.662 136.944,80.662 136.593,81.014 136.944,81.365 136.593,81.365 136.241,81.716 135.89,81.365 135.538,81.365 135.89,81.014 135.538,80.662 ; 135.538,83.825 135.89,83.825 135.89,83.473 136.593,83.473 136.593,83.825 136.944,83.825 136.944,84.527 136.593,84.527 136.593,84.879 135.89,84.879 135.89,84.527 135.538,84.527 135.538,83.825
  lines w0.305: 134.264,69.875 216.362,69.875 ; 134.264,85.687 216.362,85.687 ; 142.85,66.713 142.85,88.849 ; 151.287,66.713 151.287,88.849 ; 167.453,66.713 167.453,88.849 ; 174.037,66.713 174.037,88.849 ; 183.568,66.713 183.568,88.849 ; 201.972,66.713 201.972,88.849 ; 134.264,66.713 216.362,66.713 216.362,88.849 134.264,88.849 134.264,66.713
  text "Symbol" at 136.162,86.636 h1.83
  text "Quantity" at 143.799,86.636 h1.83
  text "Finished Hole Size" at 152.235,86.636 h1.83
  text "Plated" at 168.402,86.636 h1.83
  text "Hole Type" at 174.986,86.636 h1.83
  text "Drill Layer Pair" at 184.517,86.636 h1.83
  text "Hole Tolerance" at 202.92,86.636 h1.83
  text "25" at 143.799,83.473 h1.52
  text "11.81mil (0.300mm)" at 152.235,83.473 h1.52
  text "PTH" at 168.402,83.473 h1.52
  text "Round" at 174.986,83.473 h1.52
  text "Top Layer - Bottom Layer" at 184.517,83.473 h1.52
  text "25" at 143.799,80.311 h1.52
  text "19.69mil (0.500mm)" at 152.235,80.311 h1.52
  text "PTH" at 168.402,80.311 h1.52
  text "Round" at 174.986,80.311 h1.52
  text "Top Layer - Bottom Layer" at 184.517,80.311 h1.52
  text "7" at 143.799,77.149 h1.52
  text "40.00mil (1.016mm)" at 152.235,77.149 h1.52
  text "PTH" at 168.402,77.149 h1.52
  text "Round" at 174.986,77.149 h1.52
  text "Top Layer - Bottom Layer" at 184.517,77.149 h1.52
  text "2" at 143.799,73.986 h1.52
  text "63.00mil (1.600mm)" at 152.235,73.986 h1.52
  text "PTH" at 168.402,73.986 h1.52
  text "Round" at 174.986,73.986 h1.52
  text "Top Layer - Bottom Layer" at 184.517,73.986 h1.52
  text "11" at 143.799,70.824 h1.52
  text "122.05mil (3.100mm)" at 152.235,70.824 h1.52
  text "PTH" at 168.402,70.824 h1.52
  text "Round" at 174.986,70.824 h1.52
  text "Top Layer - Bottom Layer" at 184.517,70.824 h1.52
  text "70 Total" at 143.799,67.662 h1.52
  text ".Layer_Name" at 14.656,-21.806 h1.52
M17 Embedded Cavity:
  text ".Layer_Name" at 14.656,-21.806 h1.52
M18 Embedded Assembly:
  text ".Layer_Name" at 14.656,-21.806 h1.52
M19 Embedded Keepout:
  text ".Layer_Name" at 14.656,-21.806 h1.52

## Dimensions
0,-10.16 to 25.4,-10.16 on M2 Board Dimensions
0,0 to 0,58.42 on M2 Board Dimensions
0,0 to 87.63,0 on M2 Board Dimensions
